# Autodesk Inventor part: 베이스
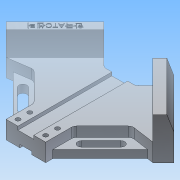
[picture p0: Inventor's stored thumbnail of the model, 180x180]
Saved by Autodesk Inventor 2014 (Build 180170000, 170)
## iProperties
Created: 2020-05
Part Number: 베이스
Material: 알루미늄 6061
Document SubType Name: Modeling
Designer: NET
Mass: 573.661 g
Surface Area: 407.289 cm^2
Volume: 211.683 cm^3
Density: 2.71 g/cm^3
Appearance: 알루미늄 - 평지
Author: NET
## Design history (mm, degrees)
sketch "스케치1"
  geometry: L1 (0, 0)-(120, 0); L2 (120, 0)-(120, 42); L3 (120, 42)-(0, 42); L4 (0, 42)-(0, 0)
  constraints: 8 end point, 2 parallel, 1 horizontal, 1 perpendicular
  dimensions: "d0" = 120 distance of L2.end L3.end; "d1" = 42 distance of L1.end L2.end
extrude "돌출1" new body sketch "스케치1" stored distance "d2" = 120; taper "d3" = 0 deg
chamfer "모따기1" distance "d7" = 40; stored, may be unused: second distance "d8" = 2, angle "d9" = 45 deg
sketch "스케치3"
  geometry: L1 (120, -80)-(80, -120) reference; L2 (0, 0)-(120, 0) reference; L3 (50, -15.65)-(15.65, -50); L4 (0, 0)-(50, 0); L5 (50, 0)-(50, -50); L6 (50, -50)-(0, -50); L7 (0, -50)-(0, 0); 1 further point
  constraints: 10 end point, 3 parallel, 2 point on line, 1 horizontal, 1 perpendicular
  dimensions: "d10" = 95 distance between parallel lines of L1 L3; "d11" = 50 distance of L2.start L4.end; "d12" = 50 distance between parallel lines of L6 L2
extrude "돌출2" cut sketch "스케치3" stored distance "d13" = 120; taper "d14" = 0 deg
sketch "스케치4"
  geometry: L1 (0, 70)-(0, 0) reference; L2 (80, 0)-(0, 0) reference; L3 (120, 40)-(80, 0) reference; L4 (120, 120)-(120, 40) reference; L5 (50, 120)-(120, 120) reference; L6 (15, 105)-(120, 105); L7 (120, 105)-(120, 0); L8 (120, 0)-(15, 0); L9 (15, 0)-(15, 105); 1 further point
  constraints: 8 end point, 2 parallel, 2 point on line, 1 horizontal, 1 perpendicular
  dimensions: "d15" = 15 distance between parallel lines of L6 L5; "d16" = 15 distance between parallel lines of L1 L9
extrude "돌출3" cut sketch "스케치4" distance "d17" = 24; taper "d18" = 0 deg
sketch "스케치5"
  geometry: L1 (0, 42)-(0, 0) reference; L2 (0, 42)-(-15, 42) reference; L3 (-5, 42)-(0, 27); L4 (0, 42)-(0, 27); L5 (-5, 42)-(0, 42); 1 further point
  constraints: 6 end point, 2 point on line, 1 collinear, 1 perpendicular
  dimensions: "d19" = 5 distance of L3.start L1.start; "d20" = 15 distance of L1.start L3.end
extrude "돌출4" cut sketch "스케치5" stored distance "d21" = 24; taper "d22" = 0 deg
sketch "스케치6"
  geometry: L1 (15, 42)-(0, 42) reference; L2 (0, 42)-(0, 0) reference; L3 (0, 42)-(5, 42); L4 (0, 27)-(5, 42); L5 (0, 42)-(0, 27)
  constraints: 6 end point, 2 point on line
  dimensions: "d23" = 5 distance of L1.end L3.end; "d24" = 15 distance of L4.start L1.end
extrude "돌출5" cut sketch "스케치6" stored distance "d25" = 24; taper "d26" = 0 deg
sketch "스케치7"
  geometry: L1 (15.65, 70)-(50, 104.35) reference; L2 (120, 40)-(80, 0) reference; L3 (32.825, 87.175)-(100, 20); L4 (38.482, 92.832)-(105.657, 25.657); L5 (27.168, 81.518)-(94.343, 14.343); L6 (38.482, 92.832)-(27.168, 81.518); L7 (94.343, 14.343)-(105.657, 25.657); 1 further point
  constraints: 10 end point, 2 midpoint, 2 parallel, 1 collinear, 1 perpendicular
  dimensions: "d27" = 8 distance between parallel lines of L4 L3; "d28" = 8 distance between parallel lines of L3 L5
extrude "돌출6" cut sketch "스케치7" distance "d29" = 3.5; taper "d30" = 0 deg
sketch "스케치8"
  geometry: L1 (0, 0)-(56.569, 0) reference; L2 (22.284, 3)-(34.284, 3); L3 (34.284, 3)-(34.284, 0); L4 (34.284, 0)-(22.284, 0); L5 (22.284, 0)-(22.284, 3); 2 further points
  constraints: 8 end point, 2 midpoint, 2 parallel, 1 horizontal, 1 perpendicular
  dimensions: "d31" = 3 distance of L2.end L3.end; "d32" = 12 distance of L3.end L4.end
extrude "돌출7" cut sketch "스케치8" stored distance "d33" = 3.5; taper "d34" = 0 deg
sketch "스케치9"
  geometry: L1 (94.343, 14.343)-(27.168, 81.518) reference; L2 (80, 0)-(15, 0) reference; L3 (15, 0)-(30, 20); L4 (30, 20)-(71.716, 20); L5 (71.716, 20)-(85.858, 5.858); L6 (0, 70)-(15, 70) reference; L7 (15, 70)-(15.65, 70) reference; L8 (15.65, 70)-(27.168, 81.518) reference; L9 (27.168, 81.518)-(94.343, 14.343) reference; L10 (94.343, 14.343)-(80, 0) reference; L11 (80, 0)-(15, 0) reference; L12 (15, 0)-(0, 0) reference; L13 (0, 0)-(0, 70) reference; L14 (15, 70)-(15, 0) reference; L15 (120, 120)-(120, 105) reference; L16 (120, 105)-(120, 40) reference; L17 (120, 40)-(105.657, 25.657) reference; L18 (105.657, 25.657)-(38.482, 92.832) reference; L19 (38.482, 92.832)-(50, 104.35) reference; L20 (50, 104.35)-(50, 105) reference; L21 (50, 105)-(50, 120) reference; L22 (50, 120)-(120, 120) reference; L23 (120, 105)-(50, 105) reference; L24 (38.482, 92.832)-(105.657, 25.657) reference; L25 (27.168, 81.518)-(38.482, 92.832) reference; L26 (94.343, 14.343)-(27.168, 81.518) reference; L27 (105.657, 25.657)-(94.343, 14.343) reference; L28 (32.825, 87.175)-(100, 20); 1 further point
  constraints: 8 end point, 2 midpoint, 2 parallel, 1 point on line
  dimensions: "d35" = 20 distance between parallel lines of L5 L28; "d36" = 20 distance between parallel lines of L2 L4; "d37" = 30 horizontal distance of L12.end L3.end
extrude "돌출8" cut sketch "스케치9" distance "d38" = 10; taper "d39" = 0 deg
node "작업 평면1"
sketch "스케치11"
  geometry: L1 (0, 0)-(0, 70) reference; L2 (0, 70)-(-10, 70) reference; 2 further points
  constraints: 1 other
  dimensions: "d47" = 35 distance from line of L2 point (-5, 35); "d48" = 5 distance from line of point (-5, 35) L1
feature "엠보싱1" sketch "스케치11" dims "d0" = 120, "d1" = 42, "d49" = 0.5, "d50" = 0
node "작업 평면2"
sketch "스케치15"
  geometry: L1 (0, 65)-(0, 0) reference; L2 (-40, -40)-(-105, -40) reference; L3 (-5, 61.25)-(-5, -5); L4 (-35, -35)-(-101.25, -35); L5 (-34.142, -34.142)-(-40, -40) reference; L6 (0, 0)-(-5.858, -5.858) reference; L7 (-70, 64.35)-(-70, 80) reference; L8 (-70, 80)-(0, 80) reference; L9 (0, 80)-(0, 65) reference; L10 (0, 65)-(-20, 50) reference; L11 (-20, 50)-(-20, 8.284) reference; L12 (-20, 8.284)-(-5.858, -5.858) reference; L13 (0, 0)-(-5.858, -5.858) reference; L14 (0, 65)-(0, 0) reference; L15 (-104.35, 30)-(-70, 64.35) reference; L16 (-120, 30)-(-104.35, 30) reference; L17 (-120, -40)-(-120, 30) reference; L18 (-105, -40)-(-120, -40) reference; L19 (-90, -20)-(-105, -40) reference; L20 (-48.284, -20)-(-90, -20) reference; L21 (-34.142, -34.142)-(-48.284, -20) reference; L22 (-34.142, -34.142)-(-40, -40) reference; L23 (-40, -40)-(-105, -40) reference; L24 (-5.858, -5.858)-(-34.142, -34.142) reference; L25 (-101.25, -35)-(-105, -40); L26 (-105, -40)-(-40, -40); L27 (-35, -35)-(-40, -40); L28 (-5, 61.25)-(0, 65); L29 (0, 65)-(0, 0); L30 (0, 0)-(-5, -5); 1 further point
  constraints: 16 end point, 6 point on line, 5 collinear, 2 parallel
  dimensions: "d66" = 5 distance between parallel lines of L1 L3; "d67" = 5 distance between parallel lines of L2 L4
extrude "돌출12" cut sketch "스케치15" stored distance "d68" = 8; taper "d69" = 0 deg
sketch "스케치18"
  geometry: L1 (120, 0)-(80, 0); L2 (120, 40)-(120, 0); L3 (100, 48.284)-(114.142, 34.142) reference; L4 (114.142, 34.142)-(105.657, 25.657) reference; L5 (105.657, 25.657)-(38.482, 92.832) reference; L6 (38.482, 92.832)-(50, 104.35) reference; L7 (50, 104.35)-(50, 105) reference; L8 (120, 105)-(50, 105) reference; L9 (120, 120)-(120, 105) reference; L10 (50, 120)-(120, 120) reference; L11 (50, 105)-(50, 120) reference; L12 (100, 90)-(100, 48.284) reference; L13 (120, 105)-(100, 90) reference; L14 (0, 70)-(15, 70) reference; L15 (15, 70)-(15.65, 70) reference; L16 (15.65, 70)-(27.168, 81.518) reference; L17 (27.168, 81.518)-(94.343, 14.343) reference; L18 (94.343, 14.343)-(85.858, 5.858) reference; L19 (85.858, 5.858)-(71.716, 20) reference; L20 (71.716, 20)-(30, 20) reference; L21 (30, 20)-(15, 0) reference; L22 (15, 0)-(0, 0) reference; L23 (0, 0)-(0, 70) reference; L24 (15, 70)-(15, 0) reference; L25 (100, 48.284)-(114.142, 34.142) reference; L26 (114.142, 34.142)-(105.657, 25.657) reference; L27 (105.657, 25.657)-(38.482, 92.832) reference; L28 (38.482, 92.832)-(50, 104.35) reference; L29 (50, 104.35)-(50, 105) reference; L30 (120, 105)-(50, 105) reference; L31 (120, 120)-(120, 105) reference; L32 (50, 120)-(120, 120) reference; L33 (50, 105)-(50, 120) reference; L34 (100, 90)-(100, 48.284) reference; L35 (120, 105)-(100, 90) reference; L36 (0, 70)-(15, 70) reference; L37 (15, 70)-(15.65, 70) reference; L38 (15.65, 70)-(27.168, 81.518) reference; L39 (27.168, 81.518)-(94.343, 14.343) reference; L40 (94.343, 14.343)-(85.858, 5.858) reference; L41 (85.858, 5.858)-(71.716, 20) reference; L42 (71.716, 20)-(30, 20) reference; L43 (30, 20)-(15, 0) reference; L44 (15, 0)-(0, 0) reference; L45 (0, 0)-(0, 70) reference; L46 (15, 70)-(15, 0) reference; L47 (120, 40)-(80, 0); L48 (105.657, 25.657)-(94.343, 14.343) reference; 2 further points
  constraints: 6 end point, 2 midpoint, 1 horizontal, 1 horizontal alignment, 1 perpendicular, 1 vertical alignment
  dimensions: "d70" = 40 distance of L2.start L1.start
extrude "돌출13" join sketch "스케치18" distance "d71" = 18; taper "d72" = 0 deg
sketch "스케치19"
  geometry: L1 (80, 0)-(120, 0) reference; L2 (120, 0)-(120, 40) reference; L3 (120, 28.284)-(91.716, 0); L4 (91.716, 0)-(120, 0); L5 (120, 28.284)-(120, 0); 1 further point
  constraints: 6 end point, 1 collinear, 1 point on line
  dimensions: "d73" = 45 deg angle of L1 L3; "d74" = 40 distance of L3.start L3.end; "d75" = 20 distance from line of L3 L1.end
extrude "돌출14" cut sketch "스케치19" stored distance "d76" = 18; taper "d77" = 0 deg
sketch "스케치20"
  geometry: L1 (91.716, 0)-(120, 28.284) reference; L2 (120, 28.284)-(120, 40) reference; L3 (120, 40)-(114.142, 34.142) reference; L4 (114.142, 34.142)-(100, 48.284) reference; L5 (100, 48.284)-(100, 90) reference; L6 (100, 90)-(120, 105) reference; L7 (50, 105)-(120, 105) reference; L8 (50, 104.35)-(50, 105) reference; L9 (38.482, 92.832)-(50, 104.35) reference; L10 (38.482, 92.832)-(105.657, 25.657) reference; L11 (105.657, 25.657)-(94.343, 14.343) reference; L12 (94.343, 14.343)-(27.168, 81.518) reference; L13 (15.65, 70)-(27.168, 81.518) reference; L14 (15, 70)-(15.65, 70) reference; L15 (15, 0)-(15, 70) reference; L16 (15, 0)-(30, 20) reference; L17 (30, 20)-(71.716, 20) reference; L18 (71.716, 20)-(85.858, 5.858) reference; L19 (85.858, 5.858)-(80, 0) reference; L20 (80, 0)-(91.716, 0) reference; L21 (120, 28.284)-(91.716, 0); L22 (50, 92.635)-(27.365, 70); L23 (0, 70)-(15, 70) reference; L24 (15, 70)-(15.65, 70) reference; L25 (15.65, 70)-(27.168, 81.518) reference; L26 (27.168, 81.518)-(94.343, 14.343) reference; L27 (94.343, 14.343)-(105.657, 25.657) reference; L28 (105.657, 25.657)-(38.482, 92.832) reference; L29 (38.482, 92.832)-(50, 104.35) reference; L30 (50, 104.35)-(50, 105) reference; L31 (120, 105)-(50, 105) reference; L32 (120, 105)-(100, 90) reference; L33 (100, 90)-(100, 48.284) reference; L34 (100, 48.284)-(114.142, 34.142) reference; L35 (114.142, 34.142)-(120, 40) reference; L36 (120, 40)-(120, 28.284) reference; L37 (120, 28.284)-(91.716, 0) reference; L38 (91.716, 0)-(80, 0) reference; L39 (80, 0)-(85.858, 5.858) reference; L40 (85.858, 5.858)-(71.716, 20) reference; L41 (71.716, 20)-(30, 20) reference; L42 (30, 20)-(15, 0) reference; L43 (15, 0)-(0, 0) reference; L44 (0, 0)-(0, 70) reference; L45 (15, 70)-(15, 0) reference; L46 (50, 105)-(50, 120) reference; L47 (50, 120)-(120, 120) reference; L48 (120, 120)-(120, 105) reference; L49 (50, 120)-(0, 120); L50 (0, 120)-(0, 70); L51 (27.365, 70)-(0, 70); L52 (50, 92.635)-(50, 120)
  constraints: 12 end point, 3 perpendicular, 2 parallel, 1 horizontal
  dimensions: "d78" = 95 distance between parallel lines of L1 L22
extrude "돌출15" cut sketch "스케치20" stored distance "d79" = 18; taper "d80" = 0 deg
fillet "모깎기1" dims "d81" = 5
sketch "스케치21"
  geometry: L1 (85.858, 5.858)-(80, 0) reference; L2 (80, 0)-(91.716, 0) reference; L3 (120, 28.284)-(120, 40) reference; L4 (120, 40)-(114.142, 34.142) reference; L5 (33.026, 75.66)-(28.83, 71.464) reference; L6 (114.142, 34.142)-(120, 28.284); L7 (85.858, 5.858)-(91.716, 0); 1 further point
  constraints: 4 end point, 1 parallel, 1 perpendicular
extrude "돌출16" cut sketch "스케치21" stored distance "d82" = 18; taper "d83" = 0 deg
sketch "스케치22"
  geometry: L1 (91.716, 0)-(120, 28.284) reference; L2 (105.657, 25.657)-(94.343, 14.343) reference; L3 (100, 20)-(105.858, 14.142); C1 r 2.25 at (83.23, 16.971); C2 r 2.25 at (91.716, 8.485); 1 further point
  constraints: 2 centre point, 2 end point, 2 midpoint
  dimensions: "d84" = 4.5 diameter of C1; "d85" = 4.5 diameter of C2; "d86" = 6 distance from line of C2.centre L1; "d87" = 12 distance of C1.centre C2.centre; "d88" = 14 distance from line of L3 C2.centre; "d89" = 14 distance from line of L3 C1.centre
extrude "돌출17" cut sketch "스케치22" distance "d90" = 8; taper "d91" = 0 deg
node "작업 평면3"
sketch "스케치23"
  geometry: L1 (120, 120)-(120, 105) reference; L2 (120, 105)-(100, 90) reference; L3 (100, 90)-(100, 48.284) reference; L4 (100, 48.284)-(120, 28.284) reference; L5 (120, 28.284)-(91.716, 0) reference; L6 (91.716, 0)-(71.716, 20) reference; L7 (71.716, 20)-(30, 20) reference; L8 (30, 20)-(15, 0) reference; L9 (15, 0)-(0, 0) reference; L10 (0, 0)-(0, 70) reference; L11 (0, 70)-(25.294, 70) reference; L12 (28.83, 71.464)-(48.536, 91.17) reference; L13 (50, 94.706)-(50, 120) reference; L14 (50, 120)-(120, 120) reference; C1 r 2.25 at (83.23, 16.971) reference; C2 r 2.25 at (91.716, 8.485) reference; C3 r 4 at (83.23, 16.971); C4 r 4 at (91.716, 8.485); A1 r 5 centre (25.294, 75) between (25.294, 70) and (28.83, 71.464) reference; A2 r 5 centre (45, 94.706) between (48.536, 91.17) and (50, 94.706) reference; 1 further point
  constraints: 2 centre point, 2 coincident
  dimensions: "d93" = 8 diameter of C3; "d94" = 8 diameter of C4
extrude "돌출18" cut sketch "스케치23" stored distance "d95" = 8; taper "d96" = 0 deg
sketch "스케치24"
  geometry: L1 (20, 71.716)-(20, 56.716) reference; L2 (20, 56.716)-(15, 52.966) reference; L3 (15, 52.966)-(15, -13.284) reference; L4 (15, -13.284)-(14.142, -14.142) reference; L5 (0, 0)-(14.142, -14.142) reference; L6 (0, 41.716)-(0, 0) reference; L7 (15, 52.966)-(0, 41.716) reference; L8 (-50, 71.716)-(20, 71.716) reference; L9 (-50, 46.421)-(-50, 71.716) reference; L10 (-71.17, 23.18)-(-51.464, 42.886) reference; L11 (-100, 21.716)-(-74.706, 21.716) reference; L12 (-100, -48.284)-(-100, 21.716) reference; L13 (-85, -48.284)-(-100, -48.284) reference; L14 (-81.25, -43.284)-(-85, -48.284) reference; L15 (-15, -43.284)-(-81.25, -43.284) reference; L16 (-14.142, -42.426)-(-15, -43.284) reference; L17 (-14.142, -42.426)-(-28.284, -28.284) reference; L18 (-28.284, -28.284)-(-70, -28.284) reference; L19 (-70, -28.284)-(-81.25, -43.284) reference; L20 (14.142, -14.142)-(20, -20) reference; L21 (20, -20)-(-8.284, -48.284) reference; L22 (-8.284, -48.284)-(-14.142, -42.426) reference; L23 (15, -13.284)-(15, -15); L24 (-15, -43.284)-(-13.284, -43.284); C1 r 4 at (-16.77, -31.314) reference; C2 r 4 at (-8.284, -39.799) reference; A1 r 5 centre (-55, 46.421) between (-51.464, 42.886) and (-50, 46.421) reference; A2 r 5 centre (-74.706, 26.716) between (-74.706, 21.716) and (-71.17, 23.18) reference; 1 further point
  constraints: 4 end point, 2 perpendicular, 2 point on line
extrude "돌출19" join sketch "스케치24" distance "d97" = 8; taper "d98" = 0 deg
sketch "스케치25"
  geometry: L1 (91.716, 0)-(120, 28.284) reference; L2 (105.657, 25.657)-(94.343, 14.343) reference; L3 (94.343, 14.343)-(100.201, 8.485); L4 (105.657, 25.657)-(111.515, 19.799); 1 further point
  constraints: 4 end point, 2 perpendicular, 2 point on line
extrude "돌출20" cut sketch "스케치25" distance "d99" = 3.5; taper "d100" = 0 deg
sketch "스케치27"
  geometry: L1 (18.75, 5)-(86.716, 5) reference; L2 (38, 12)-(66, 12); L3 (38, 8)-(66, 8); L4 (66, 16)-(38, 16); L5 (0, 0)-(0, 70) reference; A1 r 4 centre (38, 12) between (38, 16) and (38, 8); A2 r 4 centre (66, 12) between (66, 8) and (66, 16); 2 further points
  constraints: 8 end point, 4 point on circle, 4 tangent, 2 centre point, 2 parallel, 1 midpoint
  dimensions: "d101" = 28 distance of L2.start L2.end; "d104" = 8 distance between parallel lines of L3 L4; "d105" = 7 distance between parallel lines of L1 L2; "d106" = 38 distance from line of L5 L2.start
extrude "돌출21" cut sketch "스케치27" stored distance "d107" = 3.5; taper "d108" = 0 deg
sketch "스케치28"
  geometry: L1 (40, 0)-(0, 0) reference; L2 (14, 3)-(26, 3); L3 (26, 3)-(26, 0); L4 (26, 0)-(14, 0); L5 (14, 0)-(14, 3); 2 further points
  constraints: 8 end point, 2 midpoint, 2 parallel, 1 horizontal, 1 perpendicular
  dimensions: "d109" = 12 distance of L3.end L4.end; "d110" = 3 distance of L2.end L3.end
extrude "돌출22" cut sketch "스케치28" stored distance "d111" = 3.5; taper "d112" = 0 deg
fillet "모깎기2" dims "d113" = 5
node "솔리드1"
mirror "대칭1"
mirror "대칭4"
mirror "대칭5"
node "투영된 루프1"
node "투영된 루프4"
node "절단 모서리 투영1"
node "절단 모서리 투영4"
node "절단 모서리 투영6"
node "절단 모서리 투영7"
node "절단 모서리 투영8"
node "절단 모서리 투영9"
node "절단 모서리 투영10"
other parameters: "d60" = -8, "d92" = -8
